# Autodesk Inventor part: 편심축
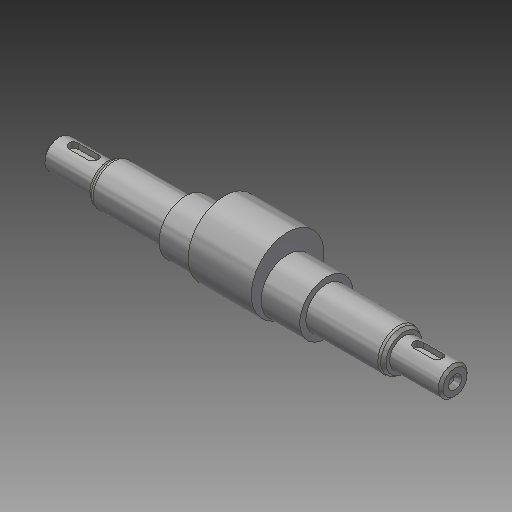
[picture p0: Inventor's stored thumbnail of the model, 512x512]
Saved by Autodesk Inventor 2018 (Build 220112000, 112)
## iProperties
Created: 2019-01
Part Number: 편심축
Material: 강철, 연강
Document SubType Name: Modeling
Designer: mduedu
Density: 7.86 g/cm^3
Appearance: 강철
Mass: 387.264 g
Surface Area: 112.62 cm^2
Volume: 49.2702 cm^3
Author: mduedu
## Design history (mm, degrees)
sketch "스케치1"
  geometry: L1 (0, 0)-(21, 0); L2 (21, 0)-(21, 6); L3 (21, 6)-(0, 6); L4 (0, 6)-(0, 0); L5 (21, 0)-(53, 0); L6 (53, 0)-(53, 8.5); L7 (53, 8.5)-(21, 8.5); L8 (21, 8.5)-(21, 0); L9 (53, 0)-(111, 0); L10 (111, 0)-(111, 11); L11 (111, 11)-(53, 11); L12 (53, 11)-(53, 0); L13 (82, 11)-(82, 0); L14 (111, 0)-(143, 0); L15 (143, 0)-(143, 8.5); L16 (143, 8.5)-(111, 8.5); L17 (111, 8.5)-(111, 0); L18 (143, 0)-(164, 0); L19 (164, 0)-(164, 6); L20 (164, 6)-(143, 6); L21 (143, 6)-(143, 0)
  constraints: 42 end point, 10 parallel, 5 horizontal, 5 perpendicular, 4 collinear, 2 midpoint
  dimensions: "d3" = 58 distance of L10.end L11.end; "d5" = 12 diameter of L3 L1; "d6" = 17 diameter of L7 L5; "d8" = 22 diameter of L11 L9; "d51" = 164 distance between parallel lines of L4 L19; "d52" = 122 distance between parallel lines of L2 L15; "d53" = 32 distance of L15.end L16.end (derived); "d54" = 32 distance of L6.end L7.end (derived)
revolve "회전1" sketch "스케치1" stored, may be unused: angle "d9" = 90 deg
node "작업 평면3"
sketch "스케치2"
  geometry: C1 r 15 at (0, 4); C2 r 11 at (0, 0); 1 further point
  constraints: 2 centre point, 1 tangent, 1 vertical alignment
  dimensions: "d11" = 4 distance of point (0, 0) C1.centre
extrude "돌출1" join sketch "스케치2" distance "d12" = 26; taper "d13" = 0 deg
node "작업 평면2"
sketch "스케치3" dims "d16" = 12
  geometry: L1 (-4.5, 2)-(3.5, 2); L2 (3.5, 2)-(3.5, -2); L3 (3.5, -2)-(-4.5, -2); L4 (-4.5, -2)-(-4.5, 2); L5 (-10.5, 8.5)-(-10.5, -8.5) reference; 3 further points
  constraints: 8 end point, 2 midpoint, 2 parallel, 2 vertical alignment, 1 horizontal, 1 horizontal alignment, 1 perpendicular, 4 other
  dimensions: "d14" = 4 distance between parallel lines of L3 L1; "d17" = 4 dimension on L5
extrude "돌출2" cut sketch "스케치3" distance "d18" = 2.5; taper "d19" = 0 deg
node "작업 평면4"
chamfer "모따기1" distance "d20" = 1.82; stored, may be unused: second distance "d21" = 2, angle "d22" = 30 deg
chamfer "모따기3" distance "d56" = 1.82; stored, may be unused: second distance "d57" = 2, angle "d58" = 30 deg
fillet "모깎기1" dims "d23" = 2
hole "구멍2" diameter "d39" = 3.242; stored, may be unused: countersink angle "d43" = 60 deg, drill point angle "d45" = 118 deg; dims "d37" = 10, "d38" = 10, "d40" = 8, "d41" = 5.51, "d42" = 2, "d44" = 10
sketch "스케치5"
  geometry: L1 (0, 0)-(2, 0); L2 (2, 0)-(2, 1.621); L3 (0, 2.776)-(0, 0); L4 (0, 2.776)-(2, 1.621); L5 (10, 1.621)-(0, 1.621) reference
  constraints: 8 end point, 1 horizontal, 1 parallel, 1 perpendicular, 1 point on line
  dimensions: "d46" = 2 distance between parallel lines of L2 L3; "d48" = 30 deg angle of L4 L1
revolve "회전2" sketch "스케치5" stored, may be unused: angle "d50" = 90 deg
chamfer "모따기2" distance "d25" = 1; stored, may be unused: second distance "d26" = 2, angle "d27" = 30 deg
node "솔리드1"
mirror "대칭1"
mirror "대칭2"
mirror "대칭3"
other parameters: "d55" = -16
